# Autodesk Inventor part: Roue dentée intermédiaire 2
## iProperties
Author: Flavien MARTY
Shininess: 41.0
PropertySet Name: _Private Model Information
Created: 2001-10
Part Number: Roue dentée intermédiaire 2
Material: Par défaut
Document SubType Name: Modélisation
Designer: Flavien MARTY
Control State: 0
Master: False
Checked Out: False
PropertySet Name: Design Tracking Control
Density: 0.0
Volumn: 0.0
Area: 0.0
PropertySet Name: Model Information
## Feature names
1. Base1
